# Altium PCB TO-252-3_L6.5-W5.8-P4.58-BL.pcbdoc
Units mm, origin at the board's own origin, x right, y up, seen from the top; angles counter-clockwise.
Board outline 19.31 x 24.51 mm, 2 copper layers (Top Layer, Bottom Layer), stack 0 mm thick; 1 components, 0 nets, 3 pads, 0 vias.
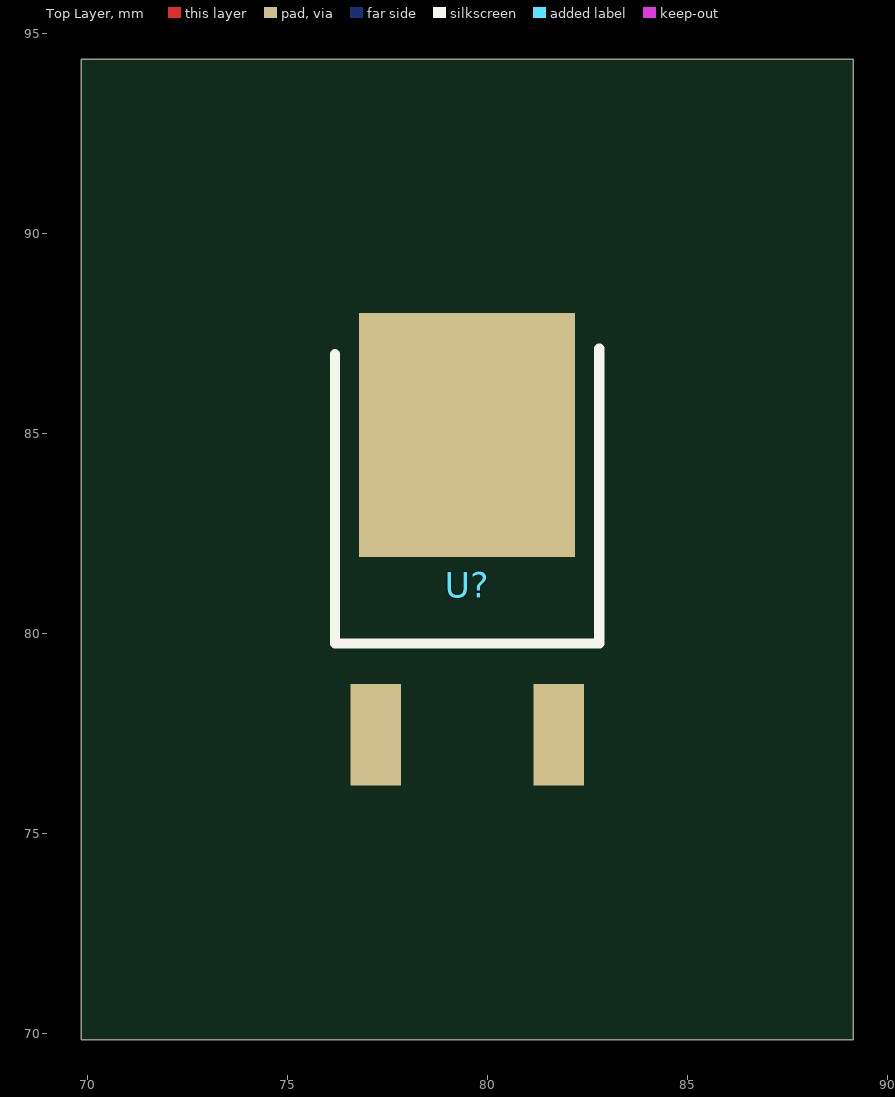
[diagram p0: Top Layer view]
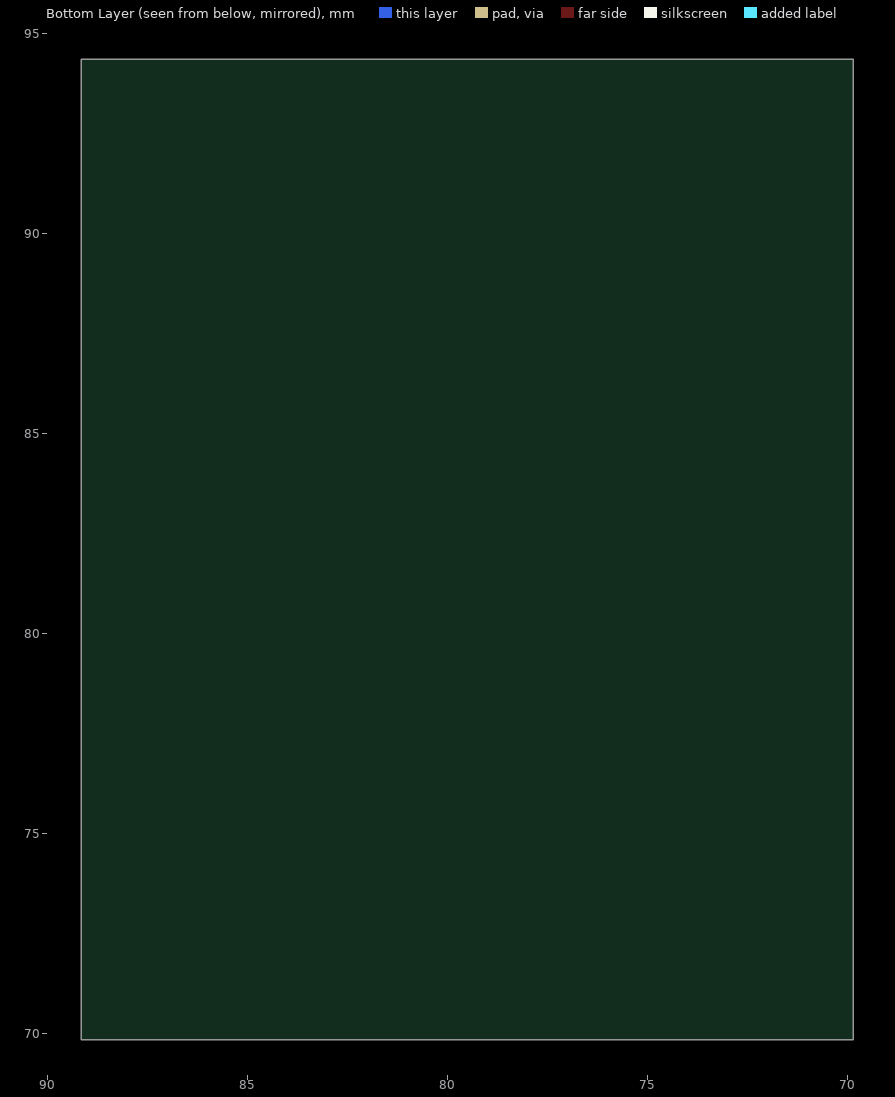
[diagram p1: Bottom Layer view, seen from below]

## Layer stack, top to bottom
Top Layer: signal copper (thickness not stored)
Bottom Layer: signal copper (thickness not stored)

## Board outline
89.155,69.85 69.85,69.85 69.85,94.364 89.155,94.364

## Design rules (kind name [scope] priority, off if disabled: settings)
PasteMaskExpansion "Paste Mask Expansion" [All] p1: expansion=0
SolderMaskExpansion "Solder Mask Expansion" [IsVia] p1: expansion=-25.4 istentingtop=TRUE
SolderMaskExpansion "Solder Mask Expansion" [All] p2: expansion=0.051 istentingtop=FALSE

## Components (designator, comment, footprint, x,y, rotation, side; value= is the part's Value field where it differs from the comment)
U? "" TO-252-3_L6.5-W5.8-P4.58-BL 79.505,81.217 r0 top

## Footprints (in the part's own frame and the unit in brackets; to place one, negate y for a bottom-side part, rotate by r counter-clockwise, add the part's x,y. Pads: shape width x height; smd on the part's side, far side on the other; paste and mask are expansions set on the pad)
TO-252-3_L6.5-W5.8-P4.58-BL [mm]
  rect 1.27x2.54 smd: 1(-2.288,-3.747) 3(2.288,-3.745)
  rect 5.4x6.1 smd: 2(-0.002,3.747)
  silkscreen extent -3.31,-1.46 3.3,5.9

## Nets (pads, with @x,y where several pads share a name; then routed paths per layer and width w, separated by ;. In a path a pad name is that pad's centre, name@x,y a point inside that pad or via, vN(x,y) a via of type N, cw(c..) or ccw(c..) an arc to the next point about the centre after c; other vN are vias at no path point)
pads on no net: U?.1 U?.2 U?.3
